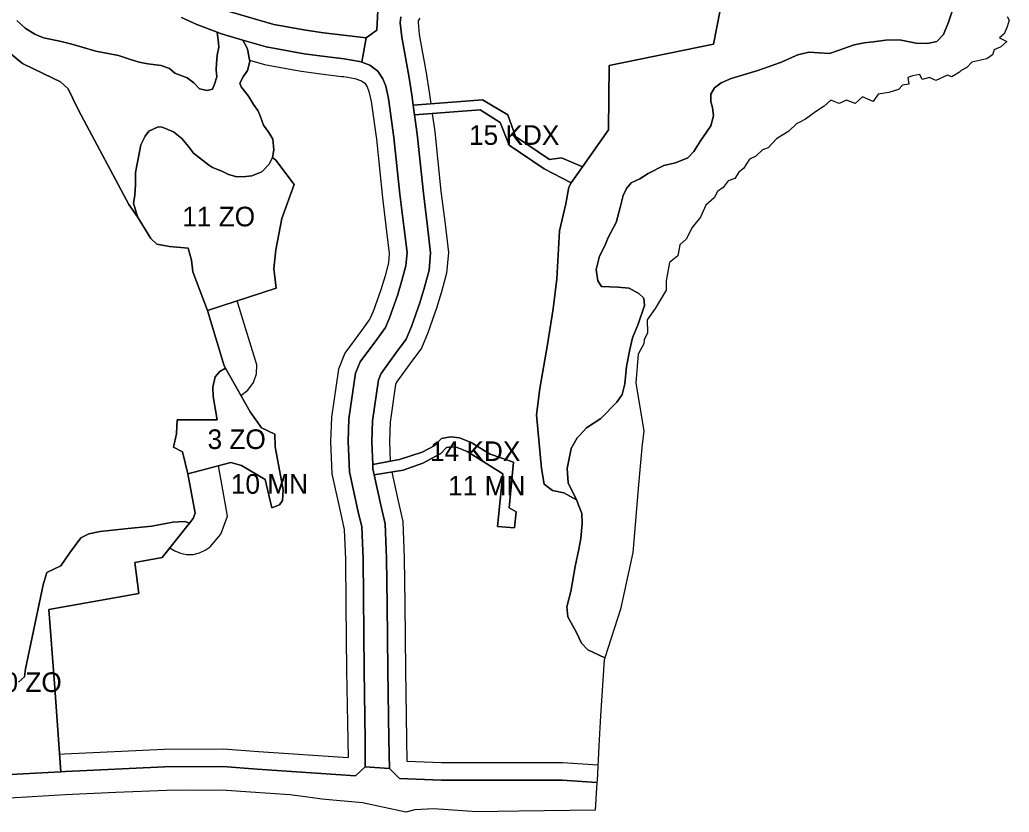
# Model space of a CAD drawing. Extents: x 7418056 to 7420315, y 5537846 to 5539505.
# Drawn here: x 7419326 to 7419831, y 5537846 to 5538250 of the extents above; entities that cross this region are included whole.
import ezdxf

# ---------------------------------------------------------------- set-up
doc = ezdxf.new("R2010")
doc.units = 0
for name, color, linetype in [('linie_rozgraniczajace', 7, 'Continuous'), ('linie_zabudowy_nieprzekraczalne', 7, 'Continuous'), ('oznaczenia_przeznaczen', 7, 'Continuous')]:
    doc.layers.add(name, color=color, linetype=linetype)

msp = doc.modelspace()

# ---------------------------------------------------------------- linework, layer by layer
at = {"layer": 'linie_rozgraniczajace'}
for points in [[(7419508.96, 5538254.97), (7419508.49, 5538244.87), (7419503.03, 5538240.98), (7419492.99, 5538242.23), (7419481.26, 5538243.57), (7419472.28, 5538244.9), (7419456, 5538247.89), (7419433.11, 5538254.43)], [(7419494.52, 5538019.83), (7419493.88, 5538035.49), (7419494.24, 5538046.86), (7419497.58, 5538070.02), (7419500.04, 5538075.84), (7419508.41, 5538087.2), (7419512.85, 5538093.29), (7419514.93, 5538098.22), (7419518.99, 5538109.68), (7419521.31, 5538117.29), (7419523.3, 5538124.73), (7419523.89, 5538131.52), (7419522.26, 5538145.08), (7419520.18, 5538161.26), (7419517.22, 5538190.25), (7419514.43, 5538210.13), (7419513.08, 5538216.3), (7419511.51, 5538220.16), (7419509.07, 5538224.04), (7419504.93, 5538227.12), (7419500.75, 5538228.54), (7419503.03, 5538240.98), (7419508.49, 5538244.87), (7419508.96, 5538254.97)], [(7419683.61, 5538255.16), (7419680.13, 5538237.77), (7419627.01, 5538226.85), (7419626.66, 5538194.04), (7419613.37, 5538175.18), (7419602.67, 5538179.88), (7419596.51, 5538179.05), (7419579.29, 5538190.7), (7419575.3, 5538201.7), (7419562.44, 5538209.41), (7419527.02, 5538206.77), (7419526.3, 5538211.92), (7419524.72, 5538221.66), (7419521.21, 5538241.42), (7419520.43, 5538248.74), (7419520.73, 5538251.65)], [(7419589.87, 5538048.88), (7419591.64, 5538062.27), (7419595.61, 5538084.72), (7419598.47, 5538102.8), (7419600.28, 5538118.25), (7419601.65, 5538142.62), (7419604.9, 5538156.43), (7419606.44, 5538164.91), (7419607.55, 5538167.04), (7419613.37, 5538175.18), (7419626.66, 5538194.04), (7419627.01, 5538226.85), (7419680.13, 5538237.77), (7419683.61, 5538255.16)], [(7419605.45, 5537951.04), (7419607.4, 5537958.79), (7419609.72, 5537971.45), (7419611.44, 5537980.43), (7419612.57, 5537985.84), (7419613.26, 5537993.44), (7419613.08, 5537998.61), (7419610.31, 5538005.48), (7419606.13, 5538014.15), (7419605.61, 5538021.4), (7419607.6, 5538031.64), (7419610.72, 5538037.08), (7419612.04, 5538038.51), (7419615.35, 5538042.13), (7419622.77, 5538046.94), (7419630.91, 5538055.3), (7419633.62, 5538059.28), (7419634.98, 5538064.63), (7419635.91, 5538073.56), (7419637.56, 5538082.08), (7419638.91, 5538088.01), (7419641.77, 5538095.01), (7419644.97, 5538104.6), (7419644.68, 5538108.31), (7419642.14, 5538110.64), (7419637.15, 5538113.45), (7419631.4, 5538113.93), (7419623.07, 5538114.31), (7419621.23, 5538117.18), (7419620.28, 5538122.88), (7419622.01, 5538129.69), (7419624.81, 5538134.96), (7419626.5, 5538139.19), (7419630.63, 5538146.95), (7419632.62, 5538154.49), (7419634.08, 5538160.7), (7419635.81, 5538164.21), (7419638.13, 5538167.03), (7419642.64, 5538169.07), (7419646.83, 5538171.9), (7419654.87, 5538175.97), (7419660.84, 5538177.36), (7419667.04, 5538179.9), (7419670.21, 5538183.04), (7419673.5, 5538188.54), (7419674.69, 5538190.27), (7419678.86, 5538196.14), (7419680.23, 5538201.22), (7419679.77, 5538205.5), (7419678.93, 5538208.62), (7419678.92, 5538212.34), (7419680.65, 5538215.57), (7419684.14, 5538218), (7419689.21, 5538220.21), (7419702.81, 5538224.35), (7419714.41, 5538228.4), (7419723.24, 5538232.31), (7419728.81, 5538233.77), (7419739.31, 5538233.05), (7419744.27, 5538234.69), (7419752.04, 5538237.43), (7419757.01, 5538238.5), (7419761.73, 5538238.98), (7419768.15, 5538239.81), (7419775.03, 5538239.95), (7419783.55, 5538238.29), (7419789.44, 5538238.1), (7419794.14, 5538239.14), (7419797.57, 5538242.73), (7419800.04, 5538248.99), (7419802.48, 5538256.12)], [(7419802.48, 5538256.12), (7419800.04, 5538248.99), (7419797.57, 5538242.73), (7419794.14, 5538239.14), (7419789.44, 5538238.1), (7419783.55, 5538238.29), (7419775.03, 5538239.95), (7419768.15, 5538239.81), (7419761.73, 5538238.98), (7419757.01, 5538238.5), (7419752.04, 5538237.43), (7419744.27, 5538234.69), (7419739.31, 5538233.05), (7419728.81, 5538233.77), (7419723.24, 5538232.31), (7419714.41, 5538228.4), (7419702.81, 5538224.35)], [(7419324.84, 5538249.93), (7419329.14, 5538245.97), (7419333.99, 5538242.92), (7419338.51, 5538241.03), (7419346.86, 5538239.3), (7419352.84, 5538237.77), (7419358.22, 5538236.22), (7419365.11, 5538234.14), (7419376.74, 5538231.95), (7419383.33, 5538229.85), (7419387.23, 5538228.53), (7419391.7, 5538227.82), (7419398.53, 5538226.92), (7419402.74, 5538225.31), (7419405.49, 5538223.06), (7419411.81, 5538220.66), (7419415.16, 5538218.13), (7419418.02, 5538215.02), (7419421.85, 5538214.15), (7419424.59, 5538214.87), (7419425.72, 5538217.38), (7419426.8, 5538221.22), (7419426.44, 5538224.65), (7419426.64, 5538227.87), (7419427.11, 5538232.14), (7419427.88, 5538236.2), (7419427.64, 5538238.26), (7419427.03, 5538243.9), (7419429.27, 5538243.05), (7419440.2, 5538239.88), (7419441.82, 5538236.83), (7419442.54, 5538235.2), (7419443.67, 5538229.03), (7419442.49, 5538224.35), (7419440.23, 5538221.06), (7419438.55, 5538217.97), (7419439.33, 5538216.09), (7419442.97, 5538211.28), (7419445.53, 5538207.09), (7419447.73, 5538203.92), (7419448.92, 5538201.28), (7419450.66, 5538196.43), (7419453.4, 5538192.71), (7419455.51, 5538189.41), (7419455.91, 5538184), (7419455.21, 5538180.09), (7419453.62, 5538176.7), (7419449.77, 5538172.66), (7419444.65, 5538170.7), (7419441.7, 5538170.28), (7419436.98, 5538170.09), (7419432.79, 5538171.4), (7419429.46, 5538173.04), (7419424.66, 5538174.91), (7419422.54, 5538176.3), (7419414.9, 5538182.2), (7419412.39, 5538185.65), (7419408.97, 5538189.64), (7419404.69, 5538193.02), (7419398.98, 5538195.45), (7419396.9, 5538195.65), (7419392.26, 5538193.39), (7419390.29, 5538190.95), (7419388.11, 5538186.43), (7419387.36, 5538182.86), (7419385.42, 5538172.43), (7419385.38, 5538166.22), (7419385.01, 5538160.6), (7419384.28, 5538156.72), (7419386.35, 5538149.71), (7419381.95, 5538156.04), (7419357.63, 5538201.64), (7419355.48, 5538205.92), (7419350.98, 5538215.05), (7419347.18, 5538218.55), (7419343.26, 5538220.45), (7419327.67, 5538227.89), (7419319.98, 5538234.34)], [(7419408.89, 5538251.39), (7419416.59, 5538247.84), (7419427.03, 5538243.9), (7419427.64, 5538238.26), (7419427.88, 5538236.2), (7419427.11, 5538232.14), (7419426.64, 5538227.87), (7419426.44, 5538224.65), (7419426.8, 5538221.22), (7419425.72, 5538217.38), (7419424.59, 5538214.87), (7419421.85, 5538214.15), (7419418.02, 5538215.02), (7419415.16, 5538218.13), (7419411.81, 5538220.66), (7419405.49, 5538223.06), (7419402.74, 5538225.31), (7419398.53, 5538226.92), (7419391.7, 5538227.82), (7419387.23, 5538228.53), (7419383.33, 5538229.85), (7419376.74, 5538231.95), (7419365.11, 5538234.14), (7419358.22, 5538236.22), (7419352.84, 5538237.77), (7419346.86, 5538239.3), (7419338.51, 5538241.03), (7419333.99, 5538242.92), (7419329.14, 5538245.97), (7419324.84, 5538249.93)], [(7419433.11, 5538254.43), (7419456, 5538247.89), (7419472.28, 5538244.9), (7419481.26, 5538243.57), (7419492.99, 5538242.23), (7419503.03, 5538240.98), (7419500.75, 5538228.54), (7419499.56, 5538228.95), (7419491.77, 5538230.36), (7419482.1, 5538231.51), (7419471.37, 5538232.9), (7419451.99, 5538236.44), (7419440.2, 5538239.88), (7419429.27, 5538243.05), (7419427.03, 5538243.9), (7419416.59, 5538247.84), (7419408.89, 5538251.39)], [(7419520.73, 5538251.65), (7419520.43, 5538248.74), (7419521.21, 5538241.42), (7419524.72, 5538221.66), (7419526.3, 5538211.92), (7419527.02, 5538206.77), (7419527.72, 5538201.81), (7419529.1, 5538191.95), (7419532.23, 5538161.81), (7419534.32, 5538144.87), (7419535.93, 5538131.47), (7419535.16, 5538122.64), (7419532.84, 5538114), (7419530.39, 5538105.93), (7419526.13, 5538093.88), (7419523.36, 5538087.34), (7419518.08, 5538080.11), (7419510.61, 5538069.94), (7419509.26, 5538066.6), (7419506.22, 5538045.81), (7419505.91, 5538035.16), (7419506.38, 5538023.53), (7419506.47, 5538021.36), (7419507.15, 5538018.24), (7419510.53, 5538002.77), (7419512.72, 5537993.27), (7419513.44, 5537975.62), (7419513.68, 5537952.17), (7419514.03, 5537918.63), (7419514.6, 5537883.3), (7419514.88, 5537868.64), (7419502.61, 5537869.48), (7419502.6, 5537883.06), (7419502.04, 5537918.47), (7419501.44, 5537975.31), (7419500.78, 5537991.67), (7419498.83, 5538000.15), (7419494.52, 5538019.83)], [(7419829.98, 5538251.95), (7419831.05, 5538250.03), (7419830.07, 5538246.68), (7419828.52, 5538243.03), (7419826.08, 5538241.01), (7419829.92, 5538239.19)], [(7419829.92, 5538239.19), (7419826.75, 5538236.35), (7419823.43, 5538234.95), (7419822.55, 5538232.36), (7419819.58, 5538230.38), (7419811.91, 5538228.64), (7419809.36, 5538225.92), (7419806.56, 5538224.31), (7419805.69, 5538223.57), (7419801.85, 5538221.11), (7419799.62, 5538221.92), (7419793.66, 5538219.28), (7419790.42, 5538220.74), (7419786.62, 5538219.85), (7419785.43, 5538222.27), (7419781.79, 5538221.67), (7419779.32, 5538220.86), (7419779.85, 5538217.48), (7419776.63, 5538216.92), (7419774.58, 5538214.76), (7419769.58, 5538213.2), (7419764.26, 5538212.22), (7419761.57, 5538208.54), (7419756.22, 5538210.99), (7419752.5, 5538207.49), (7419748.11, 5538209.24), (7419744.33, 5538207.48), (7419740.1, 5538209.22), (7419736.7, 5538206.11), (7419732.24, 5538203.32), (7419727.18, 5538199.53), (7419723.85, 5538197.78), (7419722.8, 5538197.41), (7419718.69, 5538193.36), (7419712.42, 5538189.58), (7419708.01, 5538184.99), (7419705.24, 5538183.96), (7419701.86, 5538180.69), (7419698.62, 5538179.19), (7419695.55, 5538174.35), (7419693.13, 5538172.49), (7419691.02, 5538169.24), (7419687.72, 5538168.16), (7419685.22, 5538164.77), (7419682.29, 5538162.75), (7419680.47, 5538159.45), (7419676.3, 5538155.68), (7419673.55, 5538149.6), (7419669.27, 5538144.32), (7419666.35, 5538138.32), (7419662.98, 5538135.51), (7419662.04, 5538129.9), (7419657.8, 5538126.44), (7419656.04, 5538117.12), (7419655.99, 5538112.4), (7419650.51, 5538103.1), (7419646.35, 5538097.34), (7419646.62, 5538090.71), (7419644.87, 5538087.14), (7419644.6, 5538085.09), (7419641.7, 5538079.7), (7419640.62, 5538065.22), (7419644.74, 5538040.52), (7419643.74, 5538033.92), (7419642.79, 5538022.61), (7419641.99, 5538013.11), (7419639.09, 5537978.73), (7419637.62, 5537972.41), (7419632.72, 5537949.82), (7419624.73, 5537925.02), (7419616.18, 5537929.09), (7419612.85, 5537932.4), (7419610.41, 5537937.96), (7419605.9, 5537945.89), (7419605.45, 5537951.04)], [(7419319.98, 5538234.34), (7419327.67, 5538227.89), (7419343.26, 5538220.45), (7419347.18, 5538218.55), (7419350.98, 5538215.05), (7419355.48, 5538205.92), (7419357.63, 5538201.64), (7419381.95, 5538156.04), (7419386.35, 5538149.71), (7419393.17, 5538138.69), (7419396.34, 5538135.77), (7419402.64, 5538134.63), (7419412.31, 5538133.85), (7419413.93, 5538127.74), (7419414.61, 5538121.67), (7419422.03, 5538101.94), (7419430.64, 5538073.87), (7419431.3, 5538072.69), (7419428.35, 5538070.96), (7419426.05, 5538068.13), (7419424.83, 5538063.01), (7419424.98, 5538058.15), (7419427.05, 5538046.25), (7419406.56, 5538046.27), (7419406.34, 5538039.16), (7419404.77, 5538032.38), (7419409.41, 5538030.04), (7419412.12, 5538018.75), (7419415.81, 5537998.77), (7419414.77, 5537996.04), (7419412.85, 5537993.6), (7419410.5, 5537994.4), (7419404.42, 5537994.18), (7419393.71, 5537992.15), (7419379.95, 5537990.77), (7419367.31, 5537989.34), (7419361.65, 5537988.26), (7419357.54, 5537986.07), (7419351.64, 5537978.34), (7419347.28, 5537971.81), (7419340.08, 5537968.51), (7419338.29, 5537962.22), (7419329.32, 5537919.28), (7419328.74, 5537915.33), (7419325.77, 5537912.5)], [(7419702.81, 5538224.35), (7419689.21, 5538220.21), (7419684.14, 5538218), (7419680.65, 5538215.57), (7419678.92, 5538212.34), (7419678.93, 5538208.62), (7419679.77, 5538205.5), (7419680.23, 5538201.22), (7419678.86, 5538196.14), (7419674.69, 5538190.27), (7419673.5, 5538188.54), (7419670.21, 5538183.04), (7419667.04, 5538179.9), (7419660.84, 5538177.36), (7419654.87, 5538175.97), (7419646.83, 5538171.9), (7419642.64, 5538169.07), (7419638.13, 5538167.03), (7419635.81, 5538164.21), (7419634.08, 5538160.7), (7419632.62, 5538154.49), (7419630.63, 5538146.95), (7419626.5, 5538139.19), (7419624.81, 5538134.96), (7419622.01, 5538129.69), (7419620.28, 5538122.88), (7419621.23, 5538117.18), (7419623.07, 5538114.31), (7419631.4, 5538113.93), (7419637.15, 5538113.45), (7419642.14, 5538110.64), (7419644.68, 5538108.31), (7419644.97, 5538104.6), (7419641.77, 5538095.01), (7419638.91, 5538088.01), (7419637.56, 5538082.08), (7419635.91, 5538073.56), (7419634.98, 5538064.63), (7419633.62, 5538059.28), (7419630.91, 5538055.3), (7419622.77, 5538046.94), (7419615.35, 5538042.13), (7419612.04, 5538038.51), (7419610.72, 5538037.08), (7419607.6, 5538031.64), (7419605.61, 5538021.4), (7419606.13, 5538014.15), (7419610.31, 5538005.48), (7419603.9, 5538009.12), (7419598.16, 5538010.29), (7419593.79, 5538013.56), (7419592.39, 5538021.48), (7419589.87, 5538048.88)], [(7419325.77, 5537912.5), (7419328.74, 5537915.33), (7419329.32, 5537919.28), (7419338.29, 5537962.22), (7419340.08, 5537968.51), (7419347.28, 5537971.81), (7419351.64, 5537978.34), (7419357.54, 5537986.07), (7419361.65, 5537988.26), (7419367.31, 5537989.34), (7419379.95, 5537990.77), (7419393.71, 5537992.15), (7419404.42, 5537994.18), (7419410.5, 5537994.4), (7419412.85, 5537993.6), (7419399.05, 5537976.1), (7419385.05, 5537973.58), (7419387.06, 5537957.81), (7419341.25, 5537949.56), (7419344.07, 5537911.8), (7419347.25, 5537866.84), (7419315.06, 5537865.23)], [(7419315.06, 5537865.23), (7419347.25, 5537866.84), (7419349.61, 5537866.96), (7419400.21, 5537869.35), (7419429.89, 5537869.55), (7419447.4, 5537868.26), (7419497.63, 5537864.82), (7419502.61, 5537869.48), (7419514.88, 5537868.64), (7419519.97, 5537863.44), (7419541.33, 5537862.55), (7419603, 5537862.59), (7419620.73, 5537861.48), (7419619.81, 5537847.33), (7419580.92, 5537846.78), (7419559.5, 5537846.54), (7419537.55, 5537847.93), (7419527.93, 5537847.53), (7419523.19, 5537846.28), (7419501.19, 5537850.99), (7419480.42, 5537852.95), (7419473.25, 5537853.92), (7419464.03, 5537855.08), (7419443.97, 5537856.55), (7419429.48, 5537857.54), (7419423.84, 5537857.34), (7419410.9, 5537857.51), (7419401.4, 5537857.32), (7419375.37, 5537856.26), (7419349.53, 5537855.16), (7419332.73, 5537854.1), (7419320.89, 5537853.5)]]:
    msp.add_lwpolyline(points, dxfattribs=at)
for points in [[(7419341.25, 5537949.56), (7419387.06, 5537957.81), (7419385.05, 5537973.58), (7419399.05, 5537976.1), (7419412.85, 5537993.6), (7419414.77, 5537996.04), (7419415.81, 5537998.77), (7419412.12, 5538018.75), (7419433.97, 5538024.6), (7419439.43, 5538023.04), (7419451.45, 5538015.8), (7419454.84, 5538001.42), (7419458.76, 5538003.02), (7419460.44, 5538005.22), (7419460.7, 5538010.61), (7419456.56, 5538032.49), (7419456.44, 5538038.91), (7419449.62, 5538042.25), (7419443.78, 5538050.37), (7419431.3, 5538072.69), (7419430.64, 5538073.87), (7419422.03, 5538101.94), (7419457.16, 5538113.48), (7419455.97, 5538123.44), (7419456.94, 5538133.02), (7419459.97, 5538148.9), (7419466.29, 5538166.19), (7419456.94, 5538178.62), (7419455.21, 5538180.09), (7419455.91, 5538184), (7419455.51, 5538189.41), (7419453.4, 5538192.71), (7419450.66, 5538196.43), (7419448.92, 5538201.28), (7419447.73, 5538203.92), (7419445.53, 5538207.09), (7419442.97, 5538211.28), (7419439.33, 5538216.09), (7419438.55, 5538217.97), (7419440.23, 5538221.06), (7419442.49, 5538224.35), (7419443.67, 5538229.03), (7419442.54, 5538235.2), (7419441.82, 5538236.83), (7419440.2, 5538239.88), (7419451.99, 5538236.44), (7419471.37, 5538232.9), (7419482.1, 5538231.51), (7419491.77, 5538230.36), (7419499.56, 5538228.95), (7419500.75, 5538228.54), (7419504.93, 5538227.12), (7419509.07, 5538224.04), (7419511.51, 5538220.16), (7419513.08, 5538216.3), (7419514.43, 5538210.13), (7419517.22, 5538190.25), (7419520.18, 5538161.26), (7419522.26, 5538145.08), (7419523.89, 5538131.52), (7419523.3, 5538124.73), (7419521.31, 5538117.29), (7419518.99, 5538109.68), (7419514.93, 5538098.22), (7419512.85, 5538093.29), (7419508.41, 5538087.2), (7419500.04, 5538075.84), (7419497.58, 5538070.02), (7419494.24, 5538046.86), (7419493.88, 5538035.49), (7419494.52, 5538019.83), (7419498.83, 5538000.15), (7419500.78, 5537991.67), (7419501.44, 5537975.31), (7419502.04, 5537918.47), (7419502.6, 5537883.06), (7419502.61, 5537869.48), (7419497.63, 5537864.82), (7419447.4, 5537868.26), (7419429.89, 5537869.55), (7419400.21, 5537869.35), (7419349.61, 5537866.96), (7419347.25, 5537866.84), (7419344.07, 5537911.8)], [(7419527.02, 5538206.77), (7419562.44, 5538209.41), (7419575.3, 5538201.7), (7419579.29, 5538190.7), (7419596.51, 5538179.05), (7419602.67, 5538179.88), (7419613.37, 5538175.18), (7419607.55, 5538167.04), (7419593.8, 5538174.27), (7419575.99, 5538186.29), (7419571.39, 5538197.91), (7419561.15, 5538204.35), (7419527.72, 5538201.81)], [(7419506.38, 5538023.53), (7419505.91, 5538035.16), (7419506.22, 5538045.81), (7419509.26, 5538066.6), (7419510.61, 5538069.94), (7419518.08, 5538080.11), (7419523.36, 5538087.34), (7419526.13, 5538093.88), (7419530.39, 5538105.93), (7419532.84, 5538114), (7419535.16, 5538122.64), (7419535.93, 5538131.47), (7419534.32, 5538144.87), (7419532.23, 5538161.81), (7419529.1, 5538191.95), (7419527.72, 5538201.81), (7419561.15, 5538204.35), (7419571.39, 5538197.91), (7419575.99, 5538186.29), (7419593.8, 5538174.27), (7419607.55, 5538167.04), (7419606.44, 5538164.91), (7419604.9, 5538156.43), (7419601.65, 5538142.62), (7419600.28, 5538118.25), (7419598.47, 5538102.8), (7419595.61, 5538084.72), (7419591.64, 5538062.27), (7419589.87, 5538048.88), (7419592.39, 5538021.48), (7419593.79, 5538013.56), (7419598.16, 5538010.29), (7419603.9, 5538009.12), (7419610.31, 5538005.48), (7419613.08, 5537998.61), (7419613.26, 5537993.44), (7419612.57, 5537985.84), (7419611.44, 5537980.43), (7419609.72, 5537971.45), (7419607.4, 5537958.79), (7419605.45, 5537951.04), (7419605.9, 5537945.89), (7419610.41, 5537937.96), (7419612.85, 5537932.4), (7419616.18, 5537929.09), (7419624.73, 5537925.02), (7419624.37, 5537923.93), (7419622.63, 5537895.44), (7419621.72, 5537880.03), (7419620.79, 5537862.44), (7419620.73, 5537861.48), (7419603, 5537862.59), (7419541.33, 5537862.55), (7419519.97, 5537863.44), (7419514.88, 5537868.64), (7419514.6, 5537883.3), (7419514.03, 5537918.63), (7419513.68, 5537952.17), (7419513.44, 5537975.62), (7419512.72, 5537993.27), (7419510.53, 5538002.77), (7419507.15, 5538018.24), (7419521.85, 5538020.62), (7419532.02, 5538024.27), (7419541.2, 5538029.19), (7419543.99, 5538032.16), (7419546.49, 5538032.59), (7419549.43, 5538032.26), (7419554.51, 5538030.23), (7419572.79, 5538018.69), (7419569.98, 5537991.96), (7419578.71, 5537991.19), (7419579.53, 5537999.46), (7419575.95, 5538001.48), (7419578.25, 5538024.63), (7419566.22, 5538028.75), (7419556.66, 5538034.8), (7419550.64, 5538037.15), (7419546.08, 5538037.67), (7419541.4, 5538036.72), (7419538.11, 5538033.21), (7419531.64, 5538029.74), (7419519.96, 5538026.03), (7419516.24, 5538025.47)], [(7419384.28, 5538156.72), (7419385.01, 5538160.6), (7419385.38, 5538166.22), (7419385.42, 5538172.43), (7419387.36, 5538182.86), (7419388.11, 5538186.43), (7419390.29, 5538190.95), (7419392.26, 5538193.39), (7419396.9, 5538195.65), (7419398.98, 5538195.45), (7419404.69, 5538193.02), (7419408.97, 5538189.64), (7419412.39, 5538185.65), (7419414.9, 5538182.2), (7419422.54, 5538176.3), (7419424.66, 5538174.91), (7419429.46, 5538173.04), (7419432.79, 5538171.4), (7419436.98, 5538170.09), (7419441.7, 5538170.28), (7419444.65, 5538170.7), (7419449.77, 5538172.66), (7419453.62, 5538176.7), (7419455.21, 5538180.09), (7419456.94, 5538178.62), (7419466.29, 5538166.19), (7419459.97, 5538148.9), (7419456.94, 5538133.02), (7419455.97, 5538123.44), (7419457.16, 5538113.48), (7419422.03, 5538101.94), (7419414.61, 5538121.67), (7419413.93, 5538127.74), (7419412.31, 5538133.85), (7419402.64, 5538134.63), (7419396.34, 5538135.77), (7419393.17, 5538138.69), (7419386.35, 5538149.71)], [(7419404.77, 5538032.38), (7419406.34, 5538039.16), (7419406.56, 5538046.27), (7419427.05, 5538046.25), (7419424.98, 5538058.15), (7419424.83, 5538063.01), (7419426.05, 5538068.13), (7419428.35, 5538070.96), (7419431.3, 5538072.69), (7419443.78, 5538050.37), (7419449.62, 5538042.25), (7419456.44, 5538038.91), (7419456.56, 5538032.49), (7419460.7, 5538010.61), (7419460.44, 5538005.22), (7419458.76, 5538003.02), (7419454.84, 5538001.42), (7419451.45, 5538015.8), (7419439.43, 5538023.04), (7419433.97, 5538024.6), (7419412.12, 5538018.75), (7419409.41, 5538030.04)], [(7419506.47, 5538021.36), (7419506.38, 5538023.53), (7419516.24, 5538025.47), (7419519.96, 5538026.03), (7419531.64, 5538029.74), (7419538.11, 5538033.21), (7419541.4, 5538036.72), (7419546.08, 5538037.67), (7419550.64, 5538037.15), (7419556.66, 5538034.8), (7419566.22, 5538028.75), (7419578.25, 5538024.63), (7419575.95, 5538001.48), (7419579.53, 5537999.46), (7419578.71, 5537991.19), (7419569.98, 5537991.96), (7419572.79, 5538018.69), (7419554.51, 5538030.23), (7419549.43, 5538032.26), (7419546.49, 5538032.59), (7419543.99, 5538032.16), (7419541.2, 5538029.19), (7419532.02, 5538024.27), (7419521.85, 5538020.62), (7419507.15, 5538018.24)]]:
    msp.add_lwpolyline(points, close=True, dxfattribs=at)
at = {"layer": 'linie_zabudowy_nieprzekraczalne'}
for points in [[(7419530.45, 5538251), (7419529.72, 5538250.06), (7419529.58, 5538249.65), (7419529.48, 5538248.75), (7419530.13, 5538242.69), (7419533.61, 5538223.13), (7419535.2, 5538213.26), (7419536.02, 5538207.44)], [(7419443.56, 5538229.61), (7419451.21, 5538227.42), (7419468.86, 5538224.18), (7419478.53, 5538222.76), (7419490.48, 5538221.38), (7419491.72, 5538221.23), (7419497.3, 5538220.21), (7419500.69, 5538219.06), (7419502.35, 5538217.83), (7419503.47, 5538216.04), (7419504.46, 5538213.63), (7419505.57, 5538208.55), (7419505.57, 5538208.55), (7419508.26, 5538189.41), (7419511.36, 5538159.44), (7419513.47, 5538142.34), (7419514.82, 5538131.12), (7419514.4, 5538126.3), (7419512.65, 5538119.77), (7419510.44, 5538112.49), (7419506.54, 5538101.47), (7419504.97, 5538097.76), (7419501.15, 5538092.53), (7419492.12, 5538080.25), (7419488.85, 5538072.13), (7419485.27, 5538047.65), (7419484.9, 5538035.05), (7419485.56, 5538018.68), (7419490.05, 5537998.19), (7419491.82, 5537990.47), (7419492.44, 5537975.09), (7419492.68, 5537951.96), (7419493.03, 5537918.36), (7419493.61, 5537882.93), (7419493.77, 5537874.11)], [(7419513.08, 5538216.31), (7419511.51, 5538220.17), (7419509.07, 5538224.04), (7419504.93, 5538227.13), (7419499.56, 5538228.95)], [(7419513.08, 5538216.31), (7419514.43, 5538210.13)], [(7419536.71, 5538202.5), (7419538.04, 5538193.04), (7419541.17, 5538162.83), (7419543.25, 5538145.96), (7419544.98, 5538131.62), (7419544.06, 5538121.07), (7419541.49, 5538111.52), (7419538.95, 5538103.13), (7419534.52, 5538090.62), (7419531.25, 5538082.88), (7419525.34, 5538074.79), (7419518.53, 5538065.53), (7419518.01, 5538064.24), (7419515.2, 5538045.03), (7419514.91, 5538035.22), (7419515.32, 5538025.3)], [(7419439.11, 5538058.73), (7419442.72, 5538061.48), (7419445.51, 5538065.3), (7419447.06, 5538069.78), (7419447.25, 5538074.32), (7419440.79, 5538095.23), (7419437.24, 5538106.93)], [(7419402.93, 5537981.03), (7419405.38, 5537979.44), (7419408.25, 5537978.27), (7419411.43, 5537977.67), (7419414.72, 5537977.72), (7419417.94, 5537978.44), (7419420.88, 5537979.77), (7419423.4, 5537981.58), (7419425.41, 5537983.7), (7419428.85, 5537988.06), (7419432.36, 5537997.26), (7419429.35, 5538013.56), (7419427.63, 5538022.9)], [(7419516.05, 5538019.68), (7419519.32, 5538004.75), (7419521.68, 5537994.47), (7419522.44, 5537975.85), (7419522.68, 5537952.27), (7419523.03, 5537918.75), (7419523.6, 5537883.46), (7419523.81, 5537872.29)], [(7419346.62, 5537875.83), (7419349.17, 5537875.95), (7419399.97, 5537878.35), (7419430.18, 5537878.56), (7419448.04, 5537877.24), (7419493.77, 5537874.11)], [(7419523.81, 5537872.29), (7419541.51, 5537871.56), (7419603.28, 5537871.59), (7419621.29, 5537870.47)]]:
    msp.add_lwpolyline(points, dxfattribs=at)

# ---------------------------------------------------------------- texts
at = {"layer": 'oznaczenia_przeznaczen'}
for s, p in [('15 KDX', (7419555.48, 5538186.45)), ('11 ZO', (7419409.22, 5538144.92)), ('3 ZO', (7419422.12, 5538031.42)), ('14 KDX', (7419535.6, 5538025.31)), ('10 MN', (7419434.01, 5538008.61)), ('11 MN', (7419544.86, 5538007.74)), ('10 ZO', (7419310.61, 5537907.56))]:
    msp.add_text(s, height=10, dxfattribs=at).set_placement(p)

doc.saveas('drawing.dxf')
